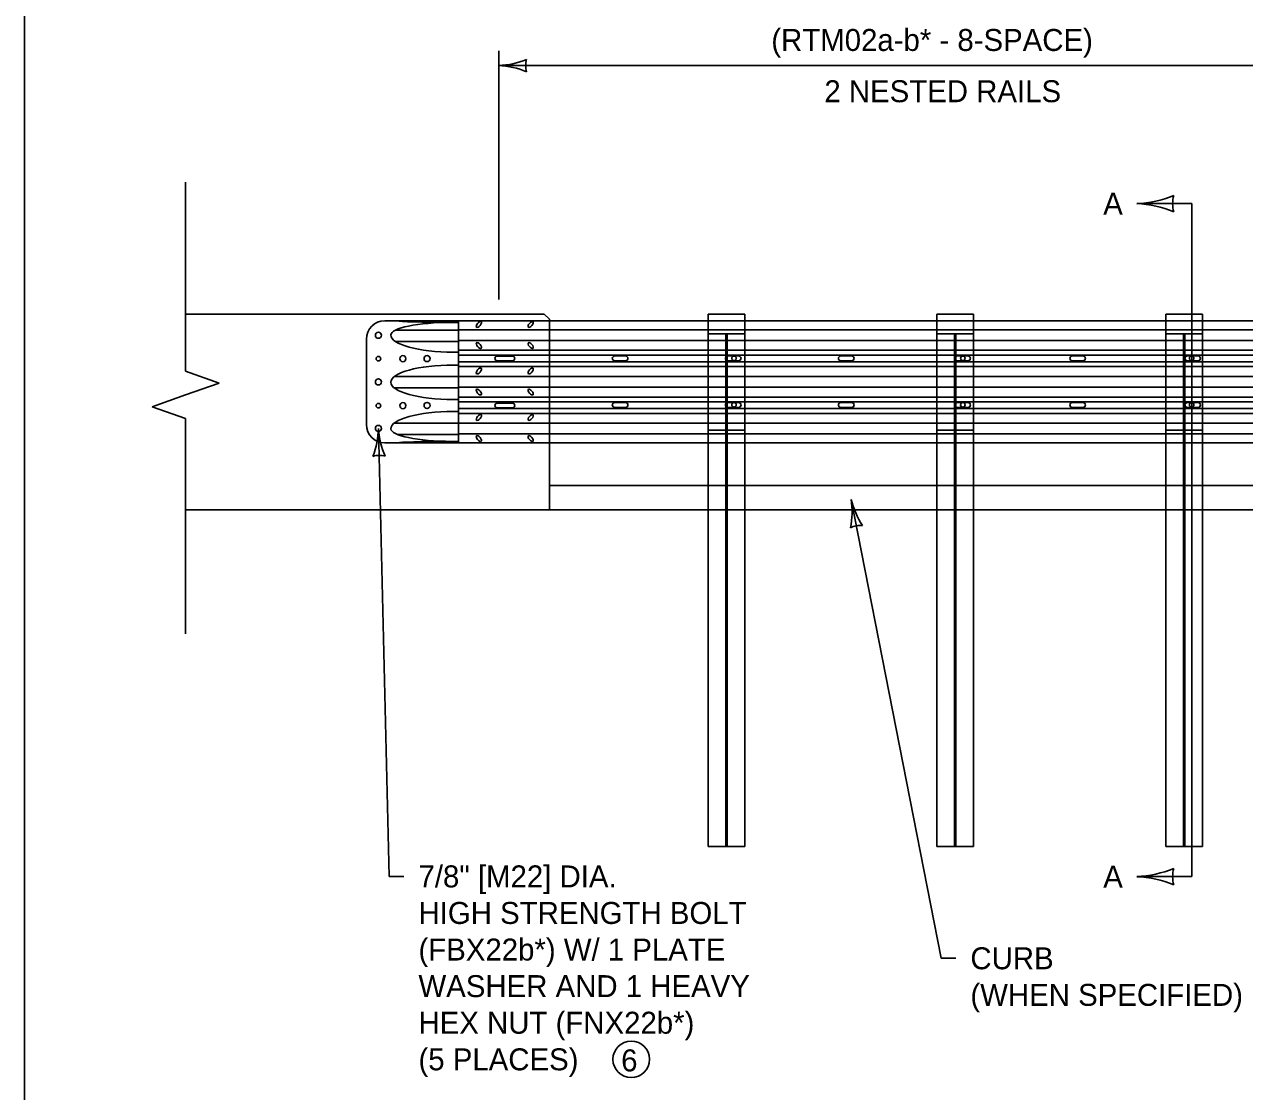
# Model space of a CAD drawing. Extents: x 49991 to 50160, y 49948 to 50051.
# Drawn here: x 49999.384 to 50002.716, y 49993.396 to 49996.312 of the extents above; entities that cross this region are included whole.
import ezdxf

# ---------------------------------------------------------------- set-up
doc = ezdxf.new("R2010")
doc.units = 0
for name, color, linetype in [('Level 1', 7, 'Continuous'), ('Level 2', 7, 'Continuous'), ('Level 3', 7, 'Continuous'), ('Level 4', 7, 'Continuous'), ('Level 6', 7, 'Continuous')]:
    doc.layers.add(name, color=color, linetype=linetype)

msp = doc.modelspace()

# ---------------------------------------------------------------- linework, layer by layer
at = {"layer": 'Level 1'}
for p, q in [((50000.8035, 49995.5207), (49999.8238, 49995.5207)), ((50000.8175, 49995.502), (50000.3675, 49995.502)), ((50000.5693, 49995.4978), (50000.5508, 49995.4978)), ((50004.3866, 49995.502), (50000.5693, 49995.502)), ((50000.5693, 49995.502), (50000.5693, 49995.1686)), ((50000.8035, 49995.5207), (50000.8175, 49995.5067)), ((50000.8175, 49995.5067), (50000.8175, 49995.502)), ((50001.2508, 49995.5204), (50001.3508, 49995.5204)), ((50001.2508, 49995.502), (50001.2508, 49995.5204)), ((50001.3508, 49995.502), (50001.3508, 49995.5204)), ((50001.8758, 49995.5204), (50001.9758, 49995.5204)), ((50001.8758, 49995.502), (50001.8758, 49995.5204)), ((50001.9758, 49995.502), (50001.9758, 49995.5204)), ((50002.5008, 49995.5204), (50002.6008, 49995.5204)), ((50002.5008, 49995.502), (50002.5008, 49995.5204)), ((50002.6008, 49995.502), (50002.6008, 49995.5204)), ((50000.5693, 49995.4764), (50000.3963, 49995.4764)), ((50004.5497, 49995.4777), (50000.5693, 49995.4777)), ((50000.3175, 49995.2189), (50000.3175, 49995.452)), ((50000.5693, 49995.4457), (50000.3967, 49995.4457)), ((50004.5497, 49995.4486), (50000.5693, 49995.4485)), ((50000.5693, 49995.4166), (50000.5549, 49995.4166)), ((50004.5497, 49995.4215), (50000.5693, 49995.4215)), ((50003.4109, 49995.4084), (50000.5693, 49995.4084)), ((50000.7165, 49995.4057), (50000.6748, 49995.4057)), ((50000.7165, 49995.4057), (50000.6748, 49995.4057)), ((50000.7165, 49995.4057), (50000.6748, 49995.4057)), ((50000.7165, 49995.4057), (50000.6748, 49995.4057)), ((50000.7165, 49995.4057), (50000.6748, 49995.4057)), ((50000.9957, 49995.4061), (50001.0252, 49995.4061)), ((50001.3046, 49995.4061), (50001.3341, 49995.4061)), ((50001.6134, 49995.406), (50001.643, 49995.406)), ((50001.9311, 49995.4061), (50001.9606, 49995.4061)), ((50002.2453, 49995.4061), (50002.2748, 49995.4061)), ((50002.5595, 49995.4061), (50002.589, 49995.4061)), ((50000.5693, 49995.3814), (50000.5549, 49995.3814)), ((50003.4095, 49995.39), (50000.5693, 49995.39)), ((50004.5499, 49995.3769), (50000.5693, 49995.3769)), ((50000.7165, 49995.3932), (50000.6748, 49995.3932)), ((50000.7165, 49995.3932), (50000.6748, 49995.3932)), ((50000.7165, 49995.3932), (50000.6748, 49995.3932)), ((50000.7165, 49995.3932), (50000.6748, 49995.3932)), ((50000.7165, 49995.3932), (50000.6748, 49995.3932)), ((50001.0252, 49995.393), (50000.9957, 49995.393)), ((50001.3341, 49995.3929), (50001.3046, 49995.3929)), ((50001.643, 49995.3929), (50001.6134, 49995.3929)), ((50001.9606, 49995.3929), (50001.9311, 49995.3929)), ((50002.2748, 49995.3929), (50002.2453, 49995.3929)), ((50002.589, 49995.3929), (50002.5595, 49995.3929)), ((50000.5693, 49995.3497), (50000.3935, 49995.3497)), ((50004.5505, 49995.3499), (50000.5693, 49995.3499)), ((50000.5693, 49995.319), (50000.3932, 49995.319)), ((50004.5497, 49995.3207), (50000.5693, 49995.3207)), ((50000.5693, 49995.2873), (50000.5549, 49995.2873)), ((50004.5497, 49995.2937), (50000.5693, 49995.2937)), ((50003.4116, 49995.2806), (50000.5693, 49995.2806)), ((50003.4083, 49995.2622), (50000.5693, 49995.2622)), ((50000.7165, 49995.277), (50000.6748, 49995.277)), ((50000.7165, 49995.277), (50000.6748, 49995.277)), ((50000.7165, 49995.277), (50000.6748, 49995.277)), ((50000.7165, 49995.277), (50000.6748, 49995.277)), ((50000.7165, 49995.277), (50000.6748, 49995.277)), ((50000.7165, 49995.2645), (50000.6748, 49995.2645)), ((50000.7165, 49995.2645), (50000.6748, 49995.2645)), ((50000.7165, 49995.2645), (50000.6748, 49995.2645)), ((50000.7165, 49995.2645), (50000.6748, 49995.2645)), ((50000.7165, 49995.2645), (50000.6748, 49995.2645)), ((50000.9957, 49995.2788), (50001.0252, 49995.2788)), ((50001.0252, 49995.2657), (50000.9957, 49995.2657)), ((50001.3046, 49995.2788), (50001.3341, 49995.2788)), ((50001.3341, 49995.2656), (50001.3046, 49995.2656)), ((50001.6134, 49995.2787), (50001.643, 49995.2787)), ((50001.643, 49995.2656), (50001.6134, 49995.2656)), ((50001.9311, 49995.2788), (50001.9606, 49995.2788)), ((50001.9606, 49995.2656), (50001.9311, 49995.2656)), ((50002.2453, 49995.2788), (50002.2748, 49995.2788)), ((50002.2748, 49995.2656), (50002.2453, 49995.2656)), ((50002.5595, 49995.2788), (50002.589, 49995.2788)), ((50002.589, 49995.2656), (50002.5595, 49995.2656)), ((50000.5693, 49995.2543), (50000.5549, 49995.2543)), ((50004.5497, 49995.2491), (50000.5693, 49995.2491)), ((50000.5693, 49995.2224), (50000.3933, 49995.2224)), ((50004.5497, 49995.2221), (50000.5693, 49995.2221)), ((50000.8175, 49995.1686), (50000.3675, 49995.1686)), ((50000.8175, 49995.1686), (50000.3675, 49995.1686)), ((50000.5693, 49995.1918), (50000.4017, 49995.1918)), ((50000.5693, 49995.1728), (50000.5508, 49995.1728)), ((50004.5497, 49995.1929), (50000.5693, 49995.1929)), ((50000.5693, 49995.1686), (50004.5497, 49995.1686)), ((50000.8175, 49995.1686), (50000.8175, 49994.9853)), ((50001.2508, 49995.052), (50001.2508, 49995.1686)), ((50001.3508, 49995.052), (50001.3508, 49995.1686)), ((50001.8758, 49995.0519), (50001.8758, 49995.1686)), ((50001.9758, 49995.0519), (50001.9758, 49995.1686)), ((50002.5008, 49995.0519), (50002.5008, 49995.1686)), ((50002.6008, 49995.0519), (50002.6008, 49995.1686)), ((50011.6716, 49995.0515), (50000.8175, 49995.052)), ((49999.8238, 49994.9854), (50011.6716, 49994.9849))]:
    msp.add_line(p, q, dxfattribs=at)
msp.add_lwpolyline([(49999.3835, 49998.9992), (50016.7501, 49998.9992), (50016.7501, 49987.7988), (49999.3835, 49987.7988)], close=True, dxfattribs=at)
for centre, radius in [((50000.3503, 49995.4626), 0.00833), ((50000.3503, 49995.3986), 0.00625), ((50000.4171, 49995.3986), 0.00833), ((50000.4171, 49995.3986), 0.00833), ((50000.4171, 49995.3986), 0.00833), ((50000.4171, 49995.3986), 0.00833), ((50000.4171, 49995.3986), 0.00833), ((50000.4832, 49995.399), 0.00833), ((50000.4832, 49995.399), 0.00833), ((50000.4832, 49995.399), 0.00833), ((50000.4832, 49995.399), 0.00833), ((50000.4832, 49995.399), 0.00833), ((50001.3216, 49995.3996), 0.00625), ((50001.9466, 49995.3996), 0.00625), ((50002.5716, 49995.3996), 0.00625), ((50000.3503, 49995.3353), 0.00833), ((50000.3503, 49995.2704), 0.00625), ((50000.4171, 49995.2704), 0.00833), ((50000.4171, 49995.2704), 0.00833), ((50000.4171, 49995.2704), 0.00833), ((50000.4171, 49995.2704), 0.00833), ((50000.4171, 49995.2704), 0.00833), ((50000.4832, 49995.2708), 0.00833), ((50000.4832, 49995.2708), 0.00833), ((50000.4832, 49995.2708), 0.00833), ((50000.4832, 49995.2708), 0.00833), ((50000.4832, 49995.2708), 0.00833), ((50001.3216, 49995.2725), 0.00625), ((50001.9466, 49995.2725), 0.00625), ((50002.5716, 49995.2725), 0.00625), ((50000.3503, 49995.208), 0.00833)]:
    msp.add_circle(centre, radius, dxfattribs=at)
for centre, radius, start, end in [((50000.3675, 49995.452), 0.05, 90, 180), ((50000.6748, 49995.3994), 0.00625, 90, 270), ((50000.6748, 49995.3994), 0.00625, 90, 270), ((50000.6748, 49995.3994), 0.00625, 90, 270), ((50000.6748, 49995.3994), 0.00625, 90, 270), ((50000.6748, 49995.3994), 0.00625, 90, 270), ((50000.7165, 49995.3994), 0.00625, 270, 90), ((50000.7165, 49995.3994), 0.00625, 270, 90), ((50000.7165, 49995.3994), 0.00625, 270, 90), ((50000.7165, 49995.3994), 0.00625, 270, 90), ((50000.7165, 49995.3994), 0.00625, 270, 90), ((50000.9957, 49995.3995), 0.00656, 90, 270), ((50001.0252, 49995.3995), 0.00656, 270, 90), ((50001.3046, 49995.3995), 0.00656, 90, 270), ((50001.3341, 49995.3995), 0.00656, 270, 90), ((50001.6134, 49995.3995), 0.00656, 90, 270), ((50001.643, 49995.3995), 0.00656, 270, 90), ((50001.9311, 49995.3995), 0.00656, 90, 270), ((50001.9606, 49995.3995), 0.00656, 270, 90), ((50002.2453, 49995.3995), 0.00656, 90, 270), ((50002.2748, 49995.3995), 0.00656, 270, 90), ((50002.5595, 49995.3995), 0.00656, 90, 270), ((50002.589, 49995.3995), 0.00656, 270, 90), ((50000.6748, 49995.2708), 0.00625, 90, 270), ((50000.6748, 49995.2708), 0.00625, 90, 270), ((50000.6748, 49995.2708), 0.00625, 90, 270), ((50000.6748, 49995.2708), 0.00625, 90, 270), ((50000.6748, 49995.2708), 0.00625, 90, 270), ((50000.7165, 49995.2708), 0.00625, 270, 90), ((50000.7165, 49995.2708), 0.00625, 270, 90), ((50000.7165, 49995.2708), 0.00625, 270, 90), ((50000.7165, 49995.2708), 0.00625, 270, 90), ((50000.7165, 49995.2708), 0.00625, 270, 90), ((50000.9957, 49995.2722), 0.00656, 90, 270), ((50001.0252, 49995.2722), 0.00656, 270, 90), ((50001.3046, 49995.2722), 0.00656, 90, 270), ((50001.3341, 49995.2722), 0.00656, 270, 90), ((50001.6134, 49995.2722), 0.00656, 90, 270), ((50001.643, 49995.2722), 0.00656, 270, 90), ((50001.9311, 49995.2722), 0.00656, 90, 270), ((50001.9606, 49995.2722), 0.00656, 270, 90), ((50002.2453, 49995.2722), 0.00656, 90, 270), ((50002.2748, 49995.2722), 0.00656, 270, 90), ((50002.5595, 49995.2722), 0.00656, 90, 270), ((50002.589, 49995.2722), 0.00656, 270, 90), ((50000.3675, 49995.2186), 0.05, 180, 270)]:
    msp.add_arc(centre, radius, start, end, dxfattribs=at)
for centre, major_axis, ratio, start_param, end_param in [((50000.5508, 49995.4634), (-0.1667, 0), 0.2062, 4.712389, 6.283185), ((50000.5508, 49995.4634), (-0.1667, 0), 0.2062, 4.712389, 6.283185), ((50000.5508, 49995.4634), (-0.1667, 0), 0.2062, 4.712389, 6.283185), ((50000.5508, 49995.4634), (-0.1667, 0), 0.2062, 4.712389, 6.283185), ((50000.5508, 49995.4634), (-0.1667, 0), 0.2062, 4.712389, 6.283185), ((50000.5508, 49995.502), (-0.1461, 0), 0.028516, 0, 1.570796), ((50000.5508, 49995.502), (-0.1461, 0), 0.028516, 0, 1.570796), ((50000.5508, 49995.502), (-0.1461, 0), 0.028516, 0, 1.570796), ((50000.5508, 49995.502), (-0.1461, 0), 0.028516, 0, 1.570796), ((50000.5508, 49995.502), (-0.1461, 0), 0.028516, 0, 1.570796), ((50000.5549, 49995.4634), (-0.1708, 0), 0.27561, 0, 1.570796), ((50000.5549, 49995.4634), (-0.1708, 0), 0.27561, 0, 1.570796), ((50000.5549, 49995.4634), (-0.1708, 0), 0.27561, 0, 1.570796), ((50000.5549, 49995.4634), (-0.1708, 0), 0.27561, 0, 1.570796), ((50000.5549, 49995.4634), (-0.1708, 0), 0.27561, 0, 1.570796), ((50000.5549, 49995.3343), (-0.1708, 0), 0.27561, 4.712389, 6.283185), ((50000.5549, 49995.3343), (-0.1708, 0), 0.27561, 4.712389, 6.283185), ((50000.5549, 49995.3343), (-0.1708, 0), 0.27561, 4.712389, 6.283185), ((50000.5549, 49995.3343), (-0.1708, 0), 0.27561, 4.712389, 6.283185), ((50000.5549, 49995.3343), (-0.1708, 0), 0.27561, 4.712389, 6.283185), ((50000.5549, 49995.3342), (-0.1708, 0), 0.27561, 0, 1.570796), ((50000.5549, 49995.3342), (-0.1708, 0), 0.27561, 0, 1.570796), ((50000.5549, 49995.3342), (-0.1708, 0), 0.27561, 0, 1.570796), ((50000.5549, 49995.3342), (-0.1708, 0), 0.27561, 0, 1.570796), ((50000.5549, 49995.3342), (-0.1708, 0), 0.27561, 0, 1.570796), ((50000.5549, 49995.2072), (-0.1708, 0), 0.27561, 4.712389, 6.283185), ((50000.5549, 49995.2072), (-0.1708, 0), 0.27561, 4.712389, 6.283185), ((50000.5549, 49995.2072), (-0.1708, 0), 0.27561, 4.712389, 6.283185), ((50000.5549, 49995.2072), (-0.1708, 0), 0.27561, 4.712389, 6.283185), ((50000.5549, 49995.2072), (-0.1708, 0), 0.27561, 4.712389, 6.283185), ((50000.5508, 49995.2072), (-0.1667, 0), 0.2062, 0, 1.570796), ((50000.5508, 49995.2072), (-0.1667, 0), 0.2062, 0, 1.570796), ((50000.5508, 49995.2072), (-0.1667, 0), 0.2062, 0, 1.570796), ((50000.5508, 49995.2072), (-0.1667, 0), 0.2062, 0, 1.570796), ((50000.5508, 49995.2072), (-0.1667, 0), 0.2062, 0, 1.570796), ((50000.5508, 49995.1686), (-0.1461, 0), 0.028516, 4.712389, 6.283185), ((50000.5508, 49995.1686), (-0.1461, 0), 0.028516, 4.712389, 6.283185), ((50000.5508, 49995.1686), (-0.1461, 0), 0.028516, 4.712389, 6.283185), ((50000.5508, 49995.1686), (-0.1461, 0), 0.028516, 4.712389, 6.283185), ((50000.5508, 49995.1686), (-0.1461, 0), 0.028516, 4.712389, 6.283185)]:
    msp.add_ellipse(centre, major_axis=major_axis, ratio=ratio, start_param=start_param, end_param=end_param, dxfattribs=at)
for centre, major_axis in [((50000.6248, 49995.4923), (-0.00633, -0.00754)), ((50000.7663, 49995.4923), (-0.00633, -0.00754)), ((50000.6248, 49995.4348), (-0.00633, 0.00754)), ((50000.7663, 49995.4348), (-0.00633, 0.00754)), ((50000.6248, 49995.365), (-0.00633, -0.00754)), ((50000.7663, 49995.365), (-0.00633, -0.00754)), ((50000.6248, 49995.3075), (-0.00633, 0.00754)), ((50000.7663, 49995.3075), (-0.00633, 0.00754)), ((50000.6248, 49995.2379), (-0.00633, -0.00754)), ((50000.7663, 49995.2379), (-0.00633, -0.00754)), ((50000.6248, 49995.1804), (-0.00633, 0.00754)), ((50000.7663, 49995.1804), (-0.00633, 0.00754))]:
    msp.add_ellipse(centre, major_axis=major_axis, ratio=0.447911, dxfattribs=at)
at = {"layer": 'Level 2'}
msp.add_circle((50001.0409, 49993.4844), 0.05, dxfattribs=at)
at = {"layer": 'Level 3'}
for p, q in [((50000.679, 49995.5607), (50000.679, 49996.2394)), ((50000.679, 49996.1994), (50003.1966, 49996.1994)), ((50000.3503, 49995.208), (50000.3798, 49993.9842)), ((50001.6414, 49995.0142), (50001.8872, 49993.7605)), ((50000.3798, 49993.9842), (50000.4198, 49993.9842)), ((50001.8872, 49993.7605), (50001.9272, 49993.7605))]:
    msp.add_line(p, q, dxfattribs=at)
for centre, radius, start, end in [((50000.6675, 49996.4322), 0.233, 272.8273, 292.0772), ((50000.6698, 49995.9773), 0.2223, 67.456, 87.6395), ((50000.8072, 49996.1994), 0.0548, 162.1388, 197.8612), ((50002.4062, 49996.1325), 0.3107, 272.8273, 292.0772), ((50002.5924, 49995.8222), 0.073, 162.1388, 197.8612), ((50002.4093, 49995.5261), 0.2964, 67.456, 87.6395), ((50000.1281, 49995.2118), 0.2223, 338.834, 359.0175), ((50000.5827, 49995.2251), 0.233, 184.2053, 203.4551), ((50000.3534, 49995.0798), 0.0548, 73.5168, 109.2391), ((50001.4216, 49994.9804), 0.2223, 348.5492, 8.7327), ((50001.8675, 49995.0702), 0.233, 193.9205, 213.1704), ((50001.666, 49994.8883), 0.0548, 83.232, 118.9544), ((50002.4062, 49994.2938), 0.3107, 272.8273, 292.0772), ((50002.5924, 49993.9835), 0.073, 162.1388, 197.8612), ((50002.4093, 49993.6873), 0.2964, 67.456, 87.6395)]:
    msp.add_arc(centre, radius, start, end, dxfattribs=at)
at = {"layer": 'Level 4'}
for p, q in [((50000.8175, 49995.502), (50000.8175, 49995.1686)), ((50001.2508, 49995.2038), (50001.2508, 49995.502)), ((50001.3508, 49995.1686), (50001.3508, 49995.502)), ((50001.8758, 49995.2038), (50001.8758, 49995.502)), ((50001.9758, 49995.1686), (50001.9758, 49995.502)), ((50002.5008, 49995.2038), (50002.5008, 49995.502)), ((50002.6008, 49995.1686), (50002.6008, 49995.502)), ((50001.2508, 49995.4663), (50001.3508, 49995.4663)), ((50001.2508, 49995.1686), (50001.2508, 49995.4663)), ((50001.2989, 49995.4663), (50001.2989, 49994.0663)), ((50001.3027, 49995.4663), (50001.3027, 49994.0663)), ((50001.8758, 49995.4663), (50001.9758, 49995.4663)), ((50001.8758, 49995.1686), (50001.8758, 49995.4663)), ((50001.9239, 49995.4663), (50001.9239, 49994.0663)), ((50001.9277, 49995.4663), (50001.9277, 49994.0663)), ((50002.5008, 49995.4663), (50002.6008, 49995.4663)), ((50002.5008, 49995.1686), (50002.5008, 49995.4663)), ((50002.5489, 49995.4663), (50002.5489, 49994.0663)), ((50002.5527, 49995.4663), (50002.5527, 49994.0663)), ((50001.2508, 49995.2038), (50001.3508, 49995.2038)), ((50001.8758, 49995.2038), (50001.9758, 49995.2038)), ((50002.5008, 49995.2038), (50002.6008, 49995.2038)), ((50001.3508, 49995.1683), (50001.3508, 49995.1683)), ((50001.9758, 49995.1683), (50001.9758, 49995.1683)), ((50002.6008, 49995.1683), (50002.6008, 49995.1683)), ((50001.2508, 49995.052), (50001.2508, 49994.0663)), ((50001.3508, 49994.0663), (50001.3508, 49995.052)), ((50001.8758, 49995.0519), (50001.8758, 49994.0663)), ((50001.9758, 49994.0663), (50001.9758, 49995.0519)), ((50002.5008, 49995.0519), (50002.5008, 49994.0663)), ((50002.6008, 49994.0663), (50002.6008, 49995.0519)), ((50001.3508, 49994.0663), (50001.2508, 49994.0663)), ((50001.9758, 49994.0663), (50001.8758, 49994.0663)), ((50002.6008, 49994.0663), (50002.5008, 49994.0663))]:
    msp.add_line(p, q, dxfattribs=at)
at = {"layer": 'Level 6'}
for p, q in [((49999.8238, 49995.3644), (49999.8238, 49995.8806)), ((50002.5715, 49995.8222), (50002.4215, 49995.8222)), ((50002.5715, 49995.8222), (50002.5715, 49993.9835)), ((50001.8758, 49995.502), (50001.8758, 49995.5204)), ((49999.8238, 49995.3644), (49999.9152, 49995.332)), ((49999.8238, 49995.2996), (49999.9152, 49995.332)), ((49999.7324, 49995.2672), (49999.8238, 49995.2996)), ((49999.7324, 49995.2672), (49999.8238, 49995.2348)), ((49999.8238, 49995.2348), (49999.8238, 49994.6465)), ((50002.5715, 49993.9835), (50002.4215, 49993.9835))]:
    msp.add_line(p, q, dxfattribs=at)

# ---------------------------------------------------------------- texts
at = {"layer": 'Level 2'}
for s, p in [(' (RTM02a-b* - 8-SPACE)', (50001.4011, 49996.2394)), ('2 NESTED RAILS', (50001.5683, 49996.0994)), ('A', (50002.33, 49995.7922)), ('7/8" [M22] DIA. ', (50000.4598, 49993.9542)), ('A', (50002.33, 49993.9535)), ('HIGH STRENGTH BOLT ', (50000.4598, 49993.8543)), ('(FBX22b*) W/ 1 PLATE ', (50000.4598, 49993.7543)), ('CURB', (50001.9672, 49993.7305)), ('WASHER AND 1 HEAVY', (50000.4598, 49993.6544)), ('(WHEN SPECIFIED)', (50001.9672, 49993.6305)), ('HEX NUT (FNX22b*) ', (50000.4598, 49993.5544)), ('(5 PLACES)', (50000.4598, 49993.4544)), ('6', (50001.0134, 49993.4515))]:
    msp.add_text(s, height=0.06, dxfattribs=at).set_placement(p)

doc.saveas('drawing.dxf')
